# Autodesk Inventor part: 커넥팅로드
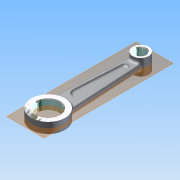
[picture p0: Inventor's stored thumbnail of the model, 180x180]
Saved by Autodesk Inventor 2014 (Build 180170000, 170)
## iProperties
Manager: KYOUNG IL JANG
Company: 한국ATC센터
Created: 2012-10
Part Number: 커넥팅로드
Document SubType Name: Modeling
Density: 1 g/cm^3
Checked By: KYOUNG IL JANG
Vendor: CBT Solutions
Designer: KYOUNG IL JANG
Material: 일반
Appearance: _시험_알루미늄 표면거칠기
Author: KYOUNG IL JANG
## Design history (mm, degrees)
sketch "스케치1"
  geometry: L1 (-19.879, 82.758)-(-19.879, 197.758); L2 (-27.379, 191.144)-(-32.379, 99.633); L3 (-12.379, 191.144)-(-7.379, 99.633); C1 r 14 at (-19.879, 82.758); C2 r 6.5 at (-19.879, 197.758); A1 r 19 centre (-19.879, 82.758) between (-20.11, 101.757) and (-19.649, 63.76) reference; A2 r 21 centre (-19.879, 82.758) between (-32.379, 99.633) and (-7.379, 99.633); A3 r 10 centre (-19.879, 197.758) between (-27.379, 191.144) and (-12.379, 191.144); 1 further point
  constraints: 6 end point, 4 centre point, 4 coincident, 4 point on circle, 2 horizontal alignment, 1 equal length, 1 vertical
  dimensions: "d0" = 28 diameter of C1; "d1" = 42 diameter of A2; "d4" = 115 distance of L1.end C1.centre; "d5" = 20 diameter of A3; "d6" = 13 diameter of C2; "d7" = 25 distance of L3.end L2.end; "d8" = 15 distance of L3.start L2.start
  node "참조1"
extrude "돌출1" new body sketch "스케치1" stored distance "d2" = 13; taper "d3" = 0 deg
extrude "돌출2" join sketch "스케치1" stored distance "d9" = 20; taper "d10" = 0 deg
extrude "돌출3" join sketch "스케치1" stored distance "d11" = 8; taper "d12" = 0 deg
sketch "스케치2"
  geometry: L1 (7.379, 99.633)-(12.379, 191.144) reference; L2 (27.379, 191.144)-(32.379, 99.633) reference; L3 (27.197, 121.158)-(24.092, 177.989); L4 (15.667, 177.989)-(12.561, 121.158); A1 r 21 centre (19.879, 82.758) between (7.379, 99.633) and (32.379, 99.633) reference; A2 r 7.329 centre (19.879, 120.758) between (12.561, 121.158) and (27.197, 121.158); A3 r 4.219 centre (19.879, 177.758) between (24.092, 177.989) and (15.667, 177.989); A4 r 10 centre (19.879, 197.758) between (12.379, 191.144) and (27.379, 191.144) reference; 2 further points
  constraints: 4 end point, 4 point on circle, 4 tangent, 2 centre point, 2 parallel, 1 coincident, 3 other
  dimensions: "d16" = 38 distance of A2.centre A1.centre; "d17" = 4 distance between parallel lines of L2 L3; "d18" = 4 distance between parallel lines of L4 L1; "d25" = 20 distance of A3.centre A4.centre
extrude "돌출4" cut sketch "스케치2" distance "d19" = 5; taper "d20" = 0 deg
fillet "모깎기1" dims "d21" = 2
fillet "모깎기2" dims "d22" = 3
fillet "모깎기3" dims "d23" = 3
chamfer "모따기1" distance "d26" = 1; stored, may be unused: second distance "d27" = 2, angle "d28" = 45 deg
chamfer "모따기2" distance "d29" = 1; stored, may be unused: second distance "d30" = 2, angle "d31" = 45 deg
node "작업 평면1"
node "솔리드1"
mirror "대칭1"
other parameters: "d13" = 5, "d14" = 5
